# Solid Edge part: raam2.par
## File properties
Author: Türk
Template: Iso Part.par
Last saved by: Türk
Revision: 27
Application: Solid Edge
Accuracy: 0,990
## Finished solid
Body 1: solid body, 6 faces, 5 edges, 0 vertices.
  Faces by surface: cylinder 3, plane 2, torus 1
  Edges by curve: circle 4, ellipse 1
Body 2: solid body, 9 faces, 9 edges, 2 vertices.
  Faces by surface: cylinder 4, spline 3, plane 2
  Edges by curve: circle 6, intersection 2, ellipse 1
Body 3: solid body, 610 faces, 1567 edges, 899 vertices, 11 internal voids.
  Faces by surface: plane 381, cylinder 155, torus 27, spline 21, swept 18, blend 4, sphere 4
  Edges by curve: line 1168, circle 314, spline 35, intersection 30, ellipse 16, curve on surface 4
Body 4: solid body, 7 faces, 6 edges, 0 vertices.
  Faces by surface: cylinder 3, plane 2, torus 2
  Edges by curve: circle 6
Body 5: solid body, 11 faces, 10 edges, 0 vertices.
  Faces by surface: spline 4, cylinder 3, plane 2, torus 2
  Edges by curve: circle 10
Body 6: solid body, 7 faces, 6 edges, 0 vertices.
  Faces by surface: cylinder 3, plane 2, torus 2
  Edges by curve: circle 6
Body 7: solid body, 7 faces, 6 edges, 0 vertices.
  Faces by surface: cylinder 3, plane 2, torus 2
  Edges by curve: circle 6
Body 8: solid body, 5 faces, 4 edges, 0 vertices.
  Faces by surface: cylinder 3, plane 2
  Edges by curve: circle 2, ellipse 2
Bounding box of the edges (mm; curved faces can reach further): 1510.388 x 4070.000 x 700.000, from (-755.1938, -700, -150) to (755.1938, 3370, 550).
Cylindrical faces by radius (mm): R5 x4, R7.5 x6, R10 x34, R12.5 x6, R15 x12, R20 x44, R25 x59, R40 x6, R50 x2, R60 x2, R100 x2
Toroidal faces (ring radius, tube radius in mm): R25 r20 x2, R25 r25 x2, R50 r7.5 x2, R50 r12.5 x2, R50 r15 x4, R50 r20 x4, R150 r15 x2, R150 r20 x2, R200 r20 x2, R200 r25 x2, R400 r7.5 x2, R400 r12.5 x2, R400 r15 x2, R400 r20 x4, R400 r25 x2
Spherical faces by radius (mm): R25 x4
Planar faces by outward normal: +x 29, +y 57, +z 25, -x 29, -y 60, -z 23, oblique 172
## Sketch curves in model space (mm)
line (-504.2913, 2553.9582, 500.1245) -> (-504.2913, 2570, 500.1245)
line (135, 2850, 150) -> (132.0505, 2850, 150)
line (-425, 0, -125) -> (-425, 25, -125)
line (-425, 25, -125) -> (-455.4523, 144.5251, -125)
line (-455.4523, 144.5251, -125) -> (-476.8912, 228.6728, -125)
line (-476.8912, 228.6728, -125) -> (-612.6174, 761.3983, -125)
arc centre (-225, 860.1543, -125) radius 400 from (-612.6174, 761.3983, -125) through (-617.9824, 785.5564, -125) to (-621.8432, 810, -125)
arc centre (-225, 860.1543, -125) radius 400 from (-621.8432, 810, -125) through (-624.21, 835.0275, -125) to (-625, 860.1543, -125)
line (-625, 860.1543, -125) -> (-625, 960, -125)
line (375, -650, -125) -> (375, -605.372, -125)
arc centre (425, -605.372, -125) radius 50 from (375, -605.372, -125) through (375.2861, -600.0307, -125) to (376.1412, -594.7506, -125)
line (376.1412, -594.7506, -125) -> (415.8705, -411.9955, -125)
arc centre (25, -327.0236, -125) radius 400 from (425, -327.0236, -125) through (422.7111, -369.7541, -125) to (415.8705, -411.9955, -125)
line (425, -220, -125) -> (425, -327.0236, -125)
line (375, -650, -25) -> (375, -642.9764, -25)
line (-749.9141, 2100, 145) -> (-749.9142, 2100, 145)
line (749.9141, 2100, 145) -> (749.9142, 2100, 145)
arc centre (749.9141, 1100, 145) radius 5 from (749.9141, 1100, 150) through (753.5962, 1100, 148.3827) to (754.9125, 1100, 144.8721)
line (605, 1100, 150) -> (749.9141, 1100, 150)
arc centre (605, 1100, 145) radius 5 from (605, 1100, 150) through (601.3631, 1100, 148.4312) to (600, 1100, 145)
line (600, 1100, -150) -> (600, 1100, 145)
line (650, 1100, -150) -> (600, 1100, -150)
spline (650, 1100, -150) -> (732.4046, 1100, -13.8518) -> (754.9125, 1100, 144.8721)
spline (749.905, 1100, 144.6459) -> (729.1623, 1100, -7.1125) -> (655, 1100, -137.721)
line (655, 1100, 144.9822) -> (655, 1100, -137.721)
line (655, 1100, 144.9822) -> (749.905, 1100, 144.6459)
line (-650, 960, 450) -> (-650, 960, 450.3463)
arc centre (-661.4189, 960, 408.1877) radius 40 from (-671.873, 960, 446.7975) through (-666.692, 960, 447.8386) to (-661.4189, 960, 448.1877)
line (650, 960, 450) -> (650, 960, 450.3463)
arc centre (661.4189, 960, 408.1877) radius 40 from (671.873, 960, 446.7975) through (666.692, 960, 447.8386) to (661.4189, 960, 448.1877)
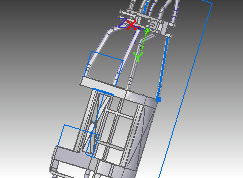
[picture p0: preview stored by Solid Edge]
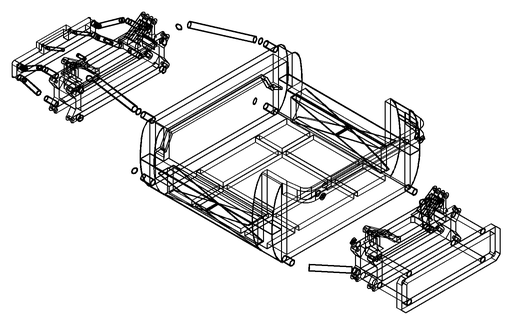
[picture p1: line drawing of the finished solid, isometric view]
